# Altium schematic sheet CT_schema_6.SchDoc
size 298 x 247 mm
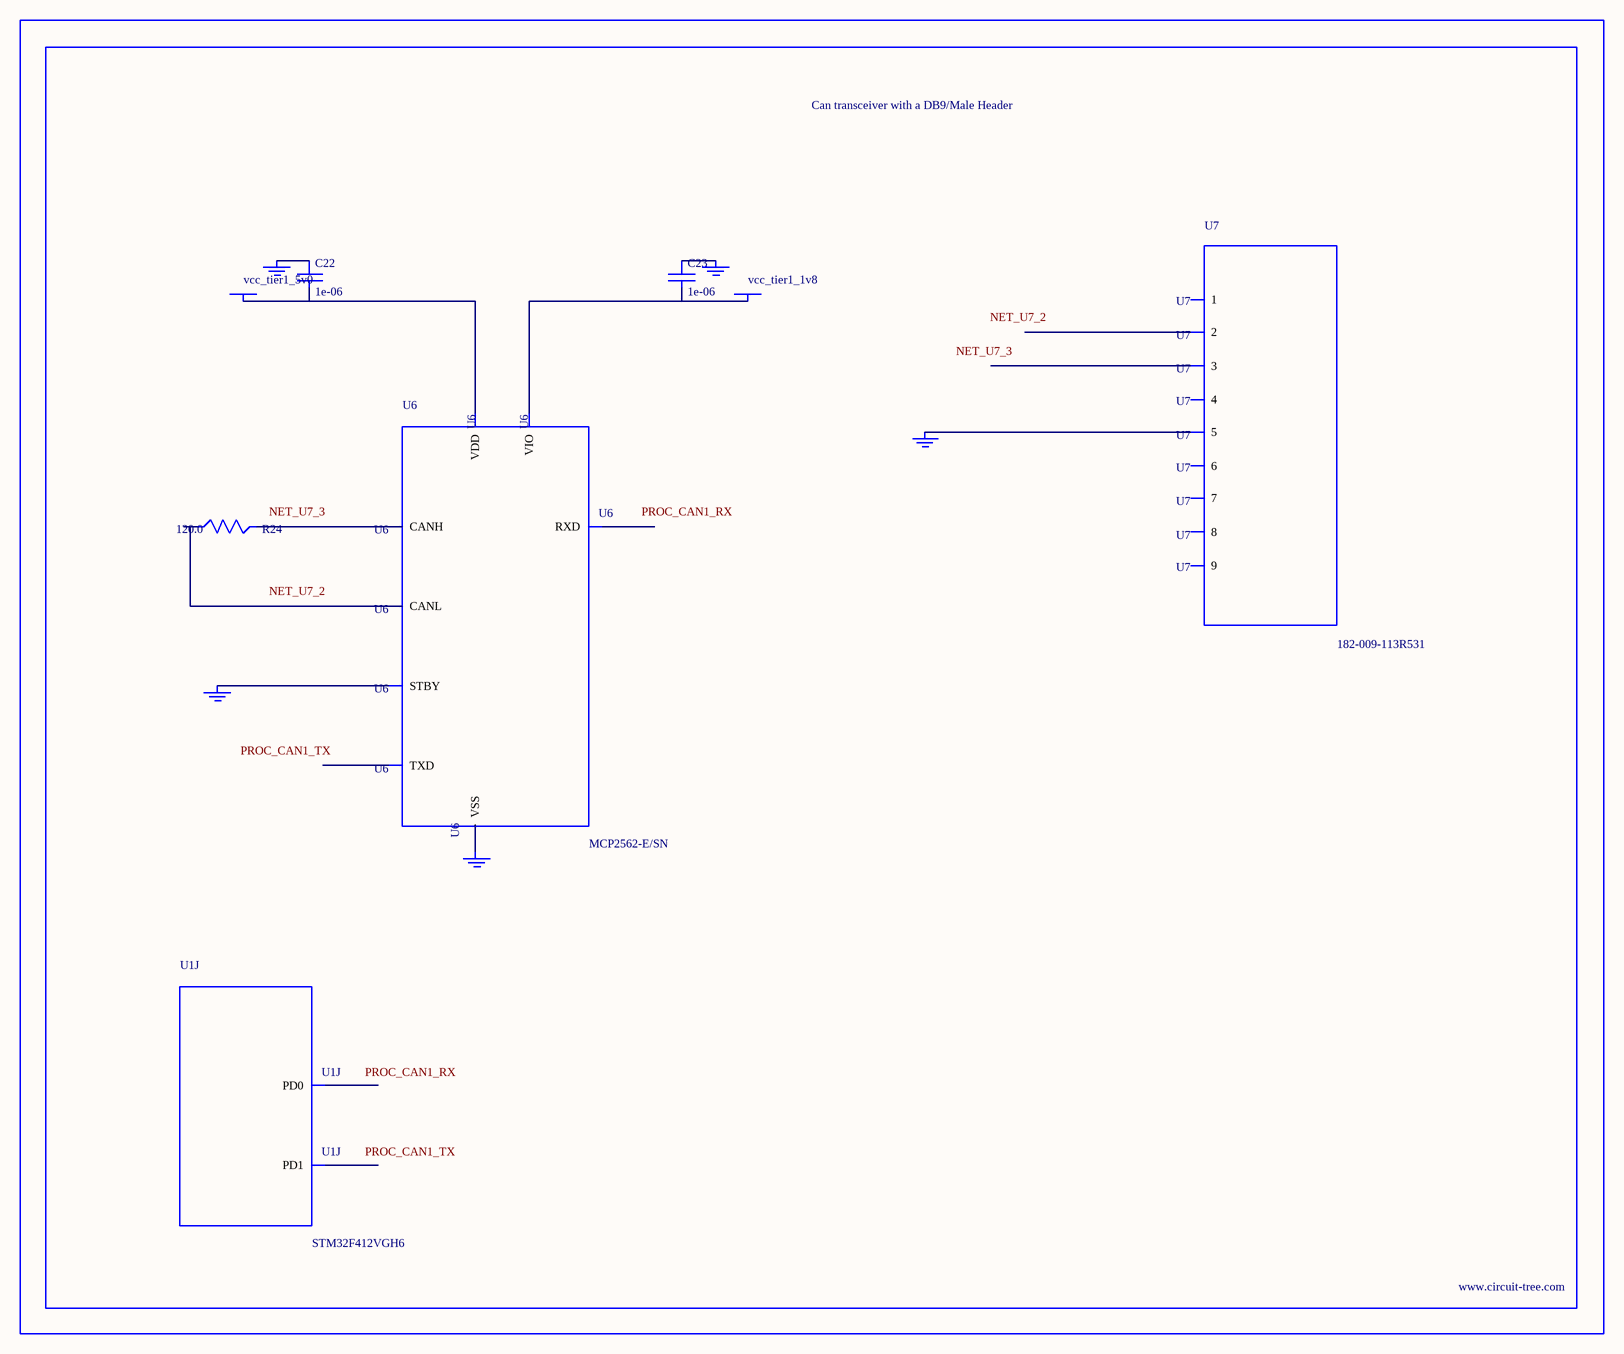
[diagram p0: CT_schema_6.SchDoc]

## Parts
BORDER5  (no value)
C22  1e-06  [C0603]
C23  1e-06  [C0603]
GND_INSTANCE_5_0  (no value)
GND_INSTANCE_5_1  (no value)
GND_INSTANCE_5_2  (no value)
GND_INSTANCE_5_3  (no value)
GND_INSTANCE_5_4  (no value)
POWER_INSTANCE_5_0  vcc_tier1_5v0
POWER_INSTANCE_5_1  vcc_tier1_1v8
R24  120.0  [R0603]
U1  STM32F412VGH6  [UFBGA100]  (part J of 11)
U6  MCP2562-E/SN  [SOIC-8]
U7  182-009-113R531  [182-009-MALE]

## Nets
NetC22_1: C22.1 GND_INSTANCE_5_0.0(GND)
NetC22_2: C22.2 POWER_INSTANCE_5_0.0(PWR) U6.3(VDD)
NetC23_1: C23.1 GND_INSTANCE_5_1.0(GND)
NetC23_2: C23.2 POWER_INSTANCE_5_1.0(PWR) U6.5(VIO)
NetGND_INSTANCE_5_2_0: GND_INSTANCE_5_2.0(GND) U6.8(STBY)
NetGND_INSTANCE_5_3_0: GND_INSTANCE_5_3.0(GND) U6.2(VSS)
NetGND_INSTANCE_5_4_0: GND_INSTANCE_5_4.0(GND) U7.5
NetR24_1: R24.1 U6.6(CANL)
NetR24_2: R24.2 U6.7(CANH)

Not connected (* = marked no-connect by the designer): U1 B9(PD1) C9(PD0); U6 1(TXD) 4(RXD); U7 1 2 3 4 6 7 8 9

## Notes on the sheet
- Labels drawn without touching a wire or pin: NET_U7_2, NET_U7_3, PROC_CAN1_RX, PROC_CAN1_TX

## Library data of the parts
BORDER5 = BORDER_PAGE5
C22 C23 = C0603C105K3RACTU
GND_INSTANCE_5_0-GND_INSTANCE_5_4 = GND
POWER_INSTANCE_5_0 POWER_INSTANCE_5_1 = PWR
R24 = RC0603JR-07120RL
